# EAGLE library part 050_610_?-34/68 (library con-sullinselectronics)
.050 DIP EDGE CARD CONNECTOR .050 [1.27mm] CONTACT CENTERS .610" INSULATEOR HEIGHT Source: .050 DIP EDGE CARD.pdf
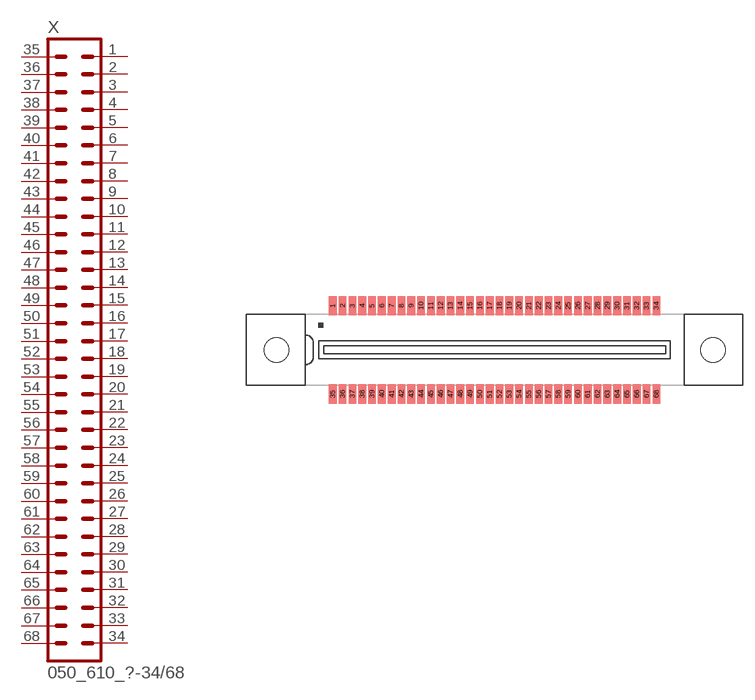
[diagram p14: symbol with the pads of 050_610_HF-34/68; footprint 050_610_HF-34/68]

Designator prefix X

## 050_610_HF-34/68 (OC_FARNELL: unknown; OC_NEWARK: unknown)  [050_610_HF-34/68]
1  1  pas
2  2  pas
3  3  pas
4  4  pas
5  5  pas
6  6  pas
7  7  pas
8  8  pas
9  9  pas
10  10  pas
11  11  pas
12  12  pas
13  13  pas
14  14  pas
15  15  pas
16  16  pas
17  17  pas
18  18  pas
19  19  pas
20  20  pas
21  21  pas
22  22  pas
23  23  pas
24  24  pas
25  25  pas
26  26  pas
27  27  pas
28  28  pas
29  29  pas
30  30  pas
31  31  pas
32  32  pas
33  33  pas
34  34  pas
35  35  pas
36  36  pas
37  37  pas
38  38  pas
39  39  pas
40  40  pas
41  41  pas
42  42  pas
43  43  pas
44  44  pas
45  45  pas
46  46  pas
47  47  pas
48  48  pas
49  49  pas
50  50  pas
51  51  pas
52  52  pas
53  53  pas
54  54  pas
55  55  pas
56  56  pas
57  57  pas
58  58  pas
59  59  pas
60  60  pas
61  61  pas
62  62  pas
63  63  pas
64  64  pas
65  65  pas
66  66  pas
67  67  pas
68  68  pas

## Footprint 050_610_HF-34/68 (pad centres in mm)
.050 DIP EDGE CARD CONNECTOR SURFACE MOUNT .050 [1.27mm] CONTACT CENTERS .610" INSULATEOR HEIGHT Source: .050 DIP EDGE CARD.pdf
smd 1 x 2.5: 1 -20.955,5.715; 2 -19.685,5.715; 3 -18.415,5.715; 4 -17.145,5.715; 5 -15.875,5.715; 6 -14.605,5.715; 7 -13.335,5.715; 8 -12.065,5.715; 9 -10.795,5.715; 10 -9.525,5.715; 11 -8.255,5.715; 12 -6.985,5.715; 13 -5.715,5.715; 14 -4.445,5.715; 15 -3.175,5.715; 16 -1.905,5.715; 17 -0.635,5.715; 18 0.635,5.715; 19 1.905,5.715; 20 3.175,5.715; 21 4.445,5.715; 22 5.715,5.715; 23 6.985,5.715; 24 8.255,5.715; 25 9.525,5.715; 26 10.795,5.715; 27 12.065,5.715; 28 13.335,5.715; 29 14.605,5.715; 30 15.875,5.715; 31 17.145,5.715; 32 18.415,5.715; 33 19.685,5.715; 34 20.955,5.715; 35 -20.955,-5.715; 36 -19.685,-5.715; 37 -18.415,-5.715; 38 -17.145,-5.715; 39 -15.875,-5.715; 40 -14.605,-5.715; 41 -13.335,-5.715; 42 -12.065,-5.715; 43 -10.795,-5.715; 44 -9.525,-5.715; 45 -8.255,-5.715; 46 -6.985,-5.715; 47 -5.715,-5.715; 48 -4.445,-5.715; 49 -3.175,-5.715; 50 -1.905,-5.715; 51 -0.635,-5.715; 52 0.635,-5.715; 53 1.905,-5.715; 54 3.175,-5.715; 55 4.445,-5.715; 56 5.715,-5.715; 57 6.985,-5.715; 58 8.255,-5.715; 59 9.525,-5.715; 60 10.795,-5.715; 61 12.065,-5.715; 62 13.335,-5.715; 63 14.605,-5.715; 64 15.875,-5.715; 65 17.145,-5.715; 66 18.415,-5.715; 67 19.685,-5.715; 68 20.955,-5.715
hole 3.18 at -28.27,0
hole 3.18 at 28.27,0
